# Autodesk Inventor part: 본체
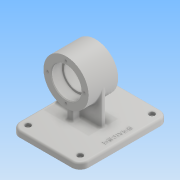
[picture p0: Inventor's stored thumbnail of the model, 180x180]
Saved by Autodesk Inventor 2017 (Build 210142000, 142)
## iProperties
Part Number: 본체
Material: 알루미늄 6061
Document SubType Name: Modeling
Designer: 603-10
Density: 2.7 g/cm^3
Appearance: 알루미늄 - 평지
Mass: 554.63 g
Surface Area: 496.231 cm^2
Volume: 205.419 cm^3
Author: 603-10
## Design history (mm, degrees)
sketch "스케치1"
  geometry: C1 r 32 at (0, 0); 1 further point
  constraints: 1 centre point, 1 coincident
  dimensions: "d0" = 64 diameter of C1
extrude "돌출1" new body sketch "스케치1" stored distance "d1" = 42; taper "d2" = 0 deg
sketch "스케치2"
  geometry: L1 (-62, -50)-(36, -50); L2 (36, -50)-(36, -59); L3 (36, -59)-(-62, -59); L4 (-62, -59)-(-62, -50); 1 further point
  constraints: 8 end point, 2 parallel, 1 horizontal, 1 perpendicular
  dimensions: "d3" = 59 distance from line of L3 point (0, 0); "d4" = 36 distance from line of L2 point (0, 0); "d5" = 9 distance of L3.end L1.start; "d6" = 98 distance of L1.start L1.end
extrude "돌출2" join sketch "스케치2" stored distance "d7" = 126; taper "d8" = 0 deg
sketch "스케치3"
  geometry: L1 (17, 0)-(-17, 0); L2 (-17, 0)-(-17, -50); L3 (-17, -50)-(17, -50); L4 (17, -50)-(17, 0); L5 (-63, -50)-(63, -50) reference; L6 (17, -31.617)-(17, 0); L7 (-17, 0)-(-17, -32.015); 2 further points
  constraints: 12 end point, 3 collinear, 1 coincident, 1 horizontal, 1 midpoint, 1 parallel, 1 perpendicular
  dimensions: "d59" = 34 distance of L1.start L1.end; "d60" = 34 distance of L2.end L3.end
extrude "돌출3" join sketch "스케치3" stored distance "d9" = 8; taper "d10" = 0 deg
sketch "스케치4"
  geometry: L1 (-32, 0)-(32, 0); L2 (32, 0)-(32, -50); L3 (32, -50)-(-32, -50); L4 (-32, -50)-(-32, 0); L5 (-62, -50)-(36, -50) reference; A1 r 32 centre (0, 0) between (-32, 0) and (32, 0) reference; 3 further points
  constraints: 8 end point, 2 parallel, 2 point on circle, 1 collinear, 1 horizontal, 1 perpendicular
  dimensions: "d42" = 64 distance of L1.start L1.end
extrude "돌출4" join sketch "스케치4" stored distance "d12" = 8; taper "d13" = 0 deg
sketch "스케치5"
  geometry: C1 r 21 at (0, 0); 1 further point
  constraints: 1 centre point, 1 coincident
  dimensions: "d14" = 42 diameter of C1
extrude "돌출5" cut sketch "스케치5" distance "d15" = 15; taper "d16" = 0 deg
sketch "스케치6"
  geometry: C1 r 18 at (0, 0); 1 further point
  constraints: 1 centre point, 1 coincident
  dimensions: "d17" = 36 diameter of C1
extrude "돌출6" cut sketch "스케치6" stored distance "d18" = 15; taper "d19" = 0 deg
sketch "스케치7" dims "d20" = 52
  geometry: C1 r 18 at (0, 0) reference; 3 further points
  constraints: 2 vertical alignment, 1 coincident, 3 other
hole "구멍1" sketch "스케치7" at (0, 26) diameter "d21" = 3.242; stored, may be unused: countersink angle "d25" = 90 deg, drill point angle "d27" = 118 deg; dims "d22" = 8, "d23" = 4, "d24" = 2, "d26" = 10
sketch "스케치8" dims "d31" = 52
  geometry: 3 further points
  constraints: 2 vertical alignment, 1 coincident, 2 other
hole "구멍2" sketch "스케치8" at (0, 26) diameter "d32" = 3.242; stored, may be unused: countersink angle "d36" = 90 deg, drill point angle "d38" = 118 deg; dims "d33" = 8, "d34" = 4, "d35" = 2, "d37" = 10
sketch "스케치9"
  geometry: L1 (105.977, -63)-(0.739, -63); L2 (49, -0.384)-(49, -137.369); L3 (0, 0)-(0, -126) reference; L4 (98, -126)-(98, 0) reference; 3 further points
  constraints: 4 end point, 1 horizontal, 1 midpoint, 1 point on line, 1 vertical
  dimensions: "d43" = 102 diameter of point (12, -12) L1; "d44" = 49 distance between parallel lines of L3 L2; "d45" = 74 diameter of point (12, -12) L2
hole "구멍3" sketch "스케치9" at (12, -12) diameter "d46" = 4.5; stored, may be unused: countersink angle "d50" = 90 deg, drill point angle "d52" = 118 deg; dims "d47" = 8, "d48" = 8, "d49" = 4.4, "d51" = 10
fillet "모깎기1" dims "d61" = 3
chamfer "모따기1" distance "d62" = 1; stored, may be unused: second distance "d63" = 2, angle "d64" = 45 deg
fillet "모깎기2" dims "d65" = 12
fillet "모깎기3" dims "d66" = 3
sketch "스케치10"
  geometry: L1 (5, -70)-(79, -70) reference; L2 (91, -58)-(91, 44) reference; 2 further points
  constraints: 1 other
  dimensions: "d67" = 63 distance from line of L1 point (81, -7); "d68" = 10 distance from line of L2 point (81, -7)
feature "엠보싱1" sketch "스케치10" dims "d69" = 0.5, "d70" = 0
node "솔리드1"
mirror "미러1"
pattern_circular "원형 패턴1" dims angle "d29" = 360 deg
pattern_circular "원형 패턴2" dims angle "d40" = 360 deg
pattern_linear "직사각형 패턴1" dims "d55" = 102, "d58" = 74
